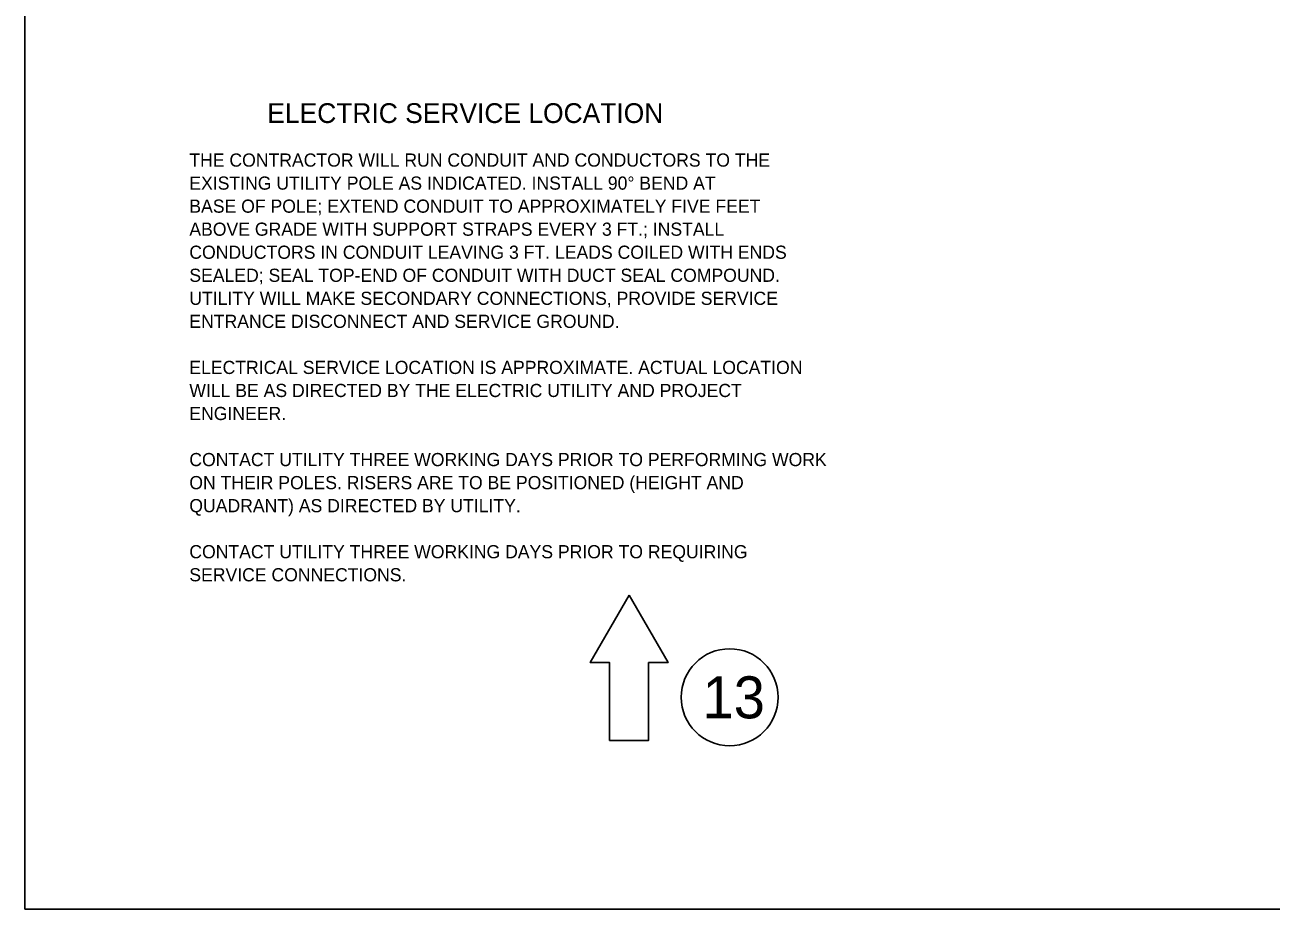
# Model space of a CAD drawing. Extents: x 100006 to 118406, y 96592 to 102182.
# Drawn here: x 105106 to 106242, y 96681 to 97487 of the extents above; entities that cross this region are included whole.
import ezdxf

# ---------------------------------------------------------------- set-up
doc = ezdxf.new("R2010")
doc.units = 0
for name, color, linetype in [('Default', 7, 'Continuous'), ('Level 7', 7, 'Continuous'), ('Level 9', 7, 'Continuous')]:
    doc.layers.add(name, color=color, linetype=linetype)

msp = doc.modelspace()

# ---------------------------------------------------------------- linework, layer by layer
at = {"layer": 'Default'}
msp.add_lwpolyline([(105106.1, 98880.7), (108305.8, 98880.7), (108305.8, 96681.1), (105106.1, 96681.1)], close=True, dxfattribs=at)
at = {"layer": 'Level 9'}
msp.add_lwpolyline([(105657, 96967.2), (105621.6, 96905.7), (105639.3, 96905.7), (105639.3, 96834.8), (105674.8, 96834.8), (105674.8, 96905.7), (105692.5, 96905.7)], close=True, dxfattribs=at)
msp.add_circle((105748.7, 96874.1), 44.2, dxfattribs=at)

# ---------------------------------------------------------------- texts
at = {"layer": 'Level 7'}
for s, height, p in [('ELECTRIC SERVICE LOCATION', 18, (105327.1, 97397.6)), ('THE CONTRACTOR WILL RUN CONDUIT AND CONDUCTORS TO THE', 12, (105256, 97357.8)), ('EXISTING UTILITY POLE AS INDICATED. INSTALL 90° BEND AT', 12, (105256, 97336.8)), ('BASE OF POLE; EXTEND CONDUIT TO APPROXIMATELY FIVE FEET', 12, (105256, 97315.8)), ('ABOVE GRADE WITH SUPPORT STRAPS EVERY 3 FT.; INSTALL', 12, (105256, 97294.8)), ('CONDUCTORS IN CONDUIT LEAVING 3 FT. LEADS COILED WITH ENDS', 12, (105256, 97273.8)), ('SEALED; SEAL TOP-END OF CONDUIT WITH DUCT SEAL COMPOUND.', 12, (105256, 97252.8)), ('UTILITY WILL MAKE SECONDARY CONNECTIONS, PROVIDE SERVICE', 12, (105256, 97231.8)), ('ENTRANCE DISCONNECT AND SERVICE GROUND.', 12, (105256, 97210.8)), ('ELECTRICAL SERVICE LOCATION IS APPROXIMATE. ACTUAL LOCATION', 12, (105256, 97168.8)), ('WILL BE AS DIRECTED BY THE ELECTRIC UTILITY AND PROJECT', 12, (105256, 97147.8)), ('ENGINEER.', 12, (105256, 97126.8)), ('CONTACT UTILITY THREE WORKING DAYS PRIOR TO PERFORMING WORK', 12, (105256, 97084.8)), ('ON THEIR POLES. RISERS ARE TO BE POSITIONED (HEIGHT AND', 12, (105256, 97063.8)), ('QUADRANT) AS DIRECTED BY UTILITY.', 12, (105256, 97042.8)), ('CONTACT UTILITY THREE WORKING DAYS PRIOR TO REQUIRING', 12, (105256, 97000.8)), ('SERVICE CONNECTIONS.', 12, (105256, 96979.8))]:
    msp.add_text(s, height=height, dxfattribs=at).set_placement(p)
at = {"layer": 'Level 9'}
msp.add_text('13', height=38.31, dxfattribs=at).set_placement((105723.9, 96854.9))

doc.saveas('drawing.dxf')
